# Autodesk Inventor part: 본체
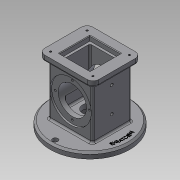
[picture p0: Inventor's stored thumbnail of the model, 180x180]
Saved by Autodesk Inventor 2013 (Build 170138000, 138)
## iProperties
Created: 2019-08
Part Number: 본체
Material: 일반
Document SubType Name: Modeling
Designer: hana-max10
Density: 1 g/cm^3
Author: hana-max10
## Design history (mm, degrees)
sketch "스케치1"
  geometry: C1 r 67.5 at (0, 0); 1 further point
  constraints: 1 centre point, 1 coincident
  dimensions: "d0" = 135 diameter of C1
extrude "돌출1" new body sketch "스케치1" distance "d2" = 10; taper "d3" = 0 deg
chamfer "모따기1" distance "d4" = 3; stored, may be unused: second distance "d5" = 2, angle "d6" = 45 deg
sketch "스케치2"
  geometry: C1 r 64.5 at (0, 0) reference; C2 r 4.5 at (0, 59); C3 r 4.5 at (-59, 0); C4 r 4.5 at (0, -59); A1 r 59 centre (0, 0) between (0, 59) and (-59, 0)
  constraints: 4 centre point, 3 point on circle, 2 vertical alignment, 1 coincident, 1 horizontal alignment
  dimensions: "d7" = 118 diameter of A1; "d9" = 9 diameter of C2; "d10" = 9 diameter of C3; "d11" = 9 diameter of C4
extrude "돌출2" cut sketch "스케치2" stored distance "d12" = 10; taper "d13" = 0 deg
sketch "스케치3"
  geometry: L1 (37, -33)-(-37, -33); L2 (-37, -33)-(-37, 33); L3 (-37, 33)-(37, 33); L4 (37, 33)-(37, -33); L5 (37, -33)-(-37, 33); L6 (-37, -33)-(37, 33); C1 r 64.5 at (0, 0) reference
  constraints: 12 end point, 2 midpoint, 2 parallel, 1 horizontal, 1 perpendicular
  dimensions: "d14" = 66 distance of L3.end L1.start; "d16" = 74 distance of L2.end L3.end
extrude "돌출3" join sketch "스케치3" distance "d17" = 88; taper "d18" = 0 deg
sketch "스케치4"
  geometry: L1 (-46, 41)-(46, 41); L2 (46, 41)-(46, -41); L3 (46, -41)-(-46, -41); L4 (-46, -41)-(-46, 41); L5 (-46, 41)-(46, -41); L6 (46, 41)-(-46, -41); 1 further point
  constraints: 12 end point, 2 midpoint, 2 parallel, 1 horizontal, 1 perpendicular
  dimensions: "d19" = 82 distance of L1.end L2.end; "d21" = 92 distance of L1.start L1.end
extrude "돌출4" join sketch "스케치4" distance "d22" = 10; taper "d23" = 0 deg
fillet "모깎기1" dims "d24" = 10
sketch "스케치5"
  geometry: A1 r 10 centre (-36, -31) between (-46, -31) and (-36, -41) reference; A2 r 10 centre (36, -31) between (36, -41) and (46, -31) reference; A3 r 10 centre (36, 31) between (46, 31) and (36, 41) reference; A4 r 10 centre (-36, 31) between (-36, 41) and (-46, 31) reference; 1 further point
hole "구멍1" sketch "스케치5" at (36, 31), (-36, 31), (-36, -31), (36, -31) diameter "d25" = 3.242; stored, may be unused: countersink angle "d29" = 90 deg, drill point angle "d31" = 118 deg; dims "d26" = 4, "d27" = 4, "d28" = 2, "d30" = 6
sketch "스케치6"
  geometry: L1 (-26, 26)-(26, 26); L2 (26, 26)-(26, -26); L3 (26, -26)-(-26, -26); L4 (-26, -26)-(-26, 26); L5 (-26, 26)-(26, -26); L6 (26, 26)-(-26, -26); 1 further point
  constraints: 12 end point, 2 midpoint, 2 parallel, 1 horizontal, 1 perpendicular
  dimensions: "d32" = 52 distance of L1.end L2.end; "d34" = 52 distance of L2.end L3.end
extrude "돌출5" cut sketch "스케치6" distance "d35" = 8; taper "d36" = 0 deg
sketch "스케치7"
  geometry: C1 r 67.5 at (0, 0) reference; C2 r 25 at (0, 0)
  constraints: 1 centre point, 1 coincident
  dimensions: "d37" = 50 diameter of C2
extrude "돌출6" cut sketch "스케치7" distance "d39" = 18; taper "d40" = 0 deg
sketch "스케치8"
  geometry: L1 (-30.5, -10)-(104.5, -10) reference; C1 r 35 at (37, 44); 2 further points
  constraints: 1 centre point, 1 midpoint, 1 vertical alignment
  dimensions: "d41" = 54 distance from line of L1 C1.centre; "d42" = 70 diameter of C1
extrude "돌출7" cut sketch "스케치8" distance "d43" = 3; taper "d44" = 0 deg
sketch "스케치9"
  geometry: L1 (-22, 22)-(22, 22); L2 (22, 22)-(22, -22); L3 (22, -22)-(-22, -22); L4 (-22, -22)-(-22, 22); L5 (-22, 22)-(22, -22); L6 (22, 22)-(-22, -22); 1 further point
  constraints: 12 end point, 2 midpoint, 2 parallel, 1 horizontal, 1 perpendicular
  dimensions: "d45" = 44 distance of L2.end L3.end; "d47" = 44 distance of L1.end L2.end
extrude "돌출8" cut sketch "스케치9" distance "d48" = 74; taper "d49" = 0 deg
fillet "모깎기2" dims "d50" = 3
sketch "스케치10"
  geometry: C1 r 35 at (0, 0) reference; C2 r 24 at (0, 0); 1 further point
  constraints: 1 centre point, 1 coincident
  dimensions: "d51" = 48 diameter of C2
extrude "돌출9" cut sketch "스케치10" stored distance "d53" = 74; taper "d54" = 0 deg
sketch "스케치11" dims "d55" = 58
  geometry: C1 r 24 at (0, 0) reference; C2 r 35 at (0, 0) reference; 3 further points
  constraints: 2 vertical alignment, 1 coincident, 2 other
hole "구멍2" sketch "스케치11" at (0, 29) diameter "d57" = 3.242; stored, may be unused: countersink angle "d61" = 90 deg, drill point angle "d63" = 118 deg; dims "d58" = 4, "d59" = 4, "d60" = 2, "d62" = 6
sketch "스케치12"
  geometry: C1 r 25 at (0, 0) reference; C2 r 12.5 at (0, 0)
  constraints: 1 centre point, 1 coincident
  dimensions: "d67" = 25 diameter of C2
extrude "돌출10" cut sketch "스케치12" stored distance "d69" = 74; taper "d70" = 0 deg
sketch "스케치13"
  geometry: L1 (10, -34.5)-(10, 100.5) reference; 2 further points
  constraints: 1 horizontal alignment
  dimensions: "d71" = 37 distance from line of point (-27, 33) L1
hole "구멍3" sketch "스케치13" at (-27, 33) diameter "d72" = 4.917; stored, may be unused: countersink angle "d76" = 90 deg, drill point angle "d78" = 0 deg; dims "d73" = 4, "d74" = 4, "d75" = 2, "d77" = 6
sketch "스케치14"
  geometry: C1 r 2.458 at (-27, 33) reference; 2 further points
  constraints: 1 horizontal alignment
  dimensions: "d79" = 43 distance of C1.centre point (-70, 33)
hole "구멍4" sketch "스케치14" at (-70, 33) diameter "d80" = 4.917; stored, may be unused: countersink angle "d84" = 90 deg, drill point angle "d86" = 0 deg; dims "d81" = 4, "d82" = 4, "d83" = 2, "d85" = 15
chamfer "모따기2" distance "d87" = 1; stored, may be unused: second distance "d88" = 2, angle "d89" = 45 deg
fillet "모깎기3" dims "d90" = 3
fillet "모깎기4" dims "d91" = 3
fillet "모깎기5" dims "d92" = 3
fillet "모깎기6" dims "d93" = 3
fillet "모깎기7" dims "d94" = 3
fillet "모깎기8" dims "d95" = 3
node "작업 평면1"
sketch "스케치15"
  geometry: C1 r 59 at (0, 0); 1 further point
  constraints: 1 centre point, 1 coincident, 1 other
  dimensions: "d97" = 118 diameter of C1
feature "엠보싱1" sketch "스케치15" dims "d14" = 66, "d16" = 74, "d99" = 0.5, "d100" = 0
node "솔리드1"
mirror "대칭1"
pattern_circular "원형 패턴1" dims angle "d65" = 360 deg
mirror "대칭2"
other parameters: "d96" = 241.75
